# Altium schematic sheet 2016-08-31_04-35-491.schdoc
size 331 x 134 mm; SheetNumber: 1; SheetTotal: 1
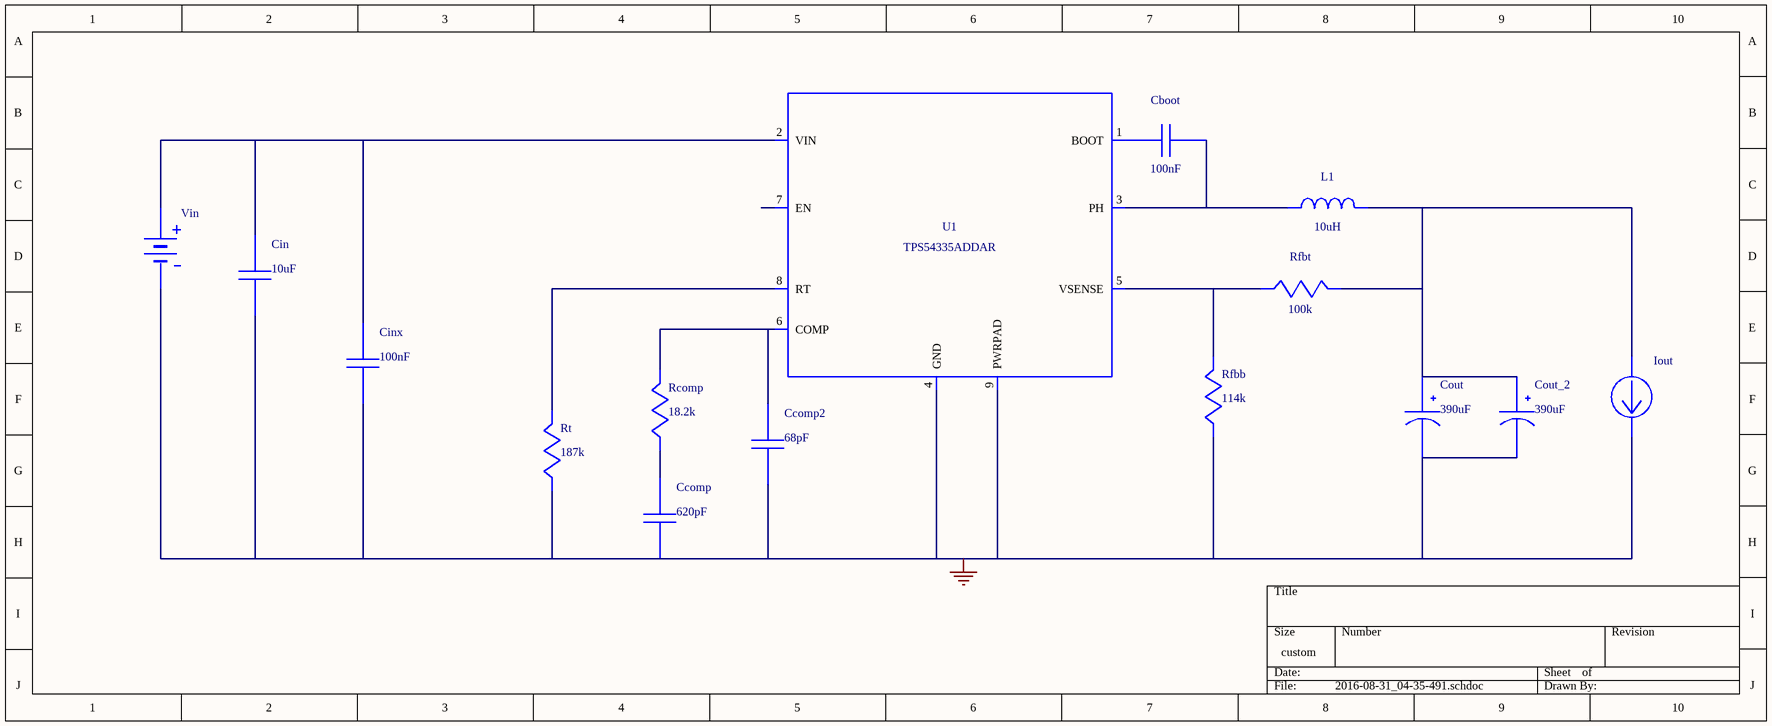
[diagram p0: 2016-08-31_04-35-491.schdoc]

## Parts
Cboot  value 100nF  (hidden comment: C0805C104K5RACTU)
Ccomp  value 620pF  (hidden comment: CL21C621JBCNNNC)
Ccomp2  value 68pF  (hidden comment: C0805C680K5GACTU)
Cin  value 10uF  (hidden comment: GRM31CR71E106KA12L)
Cinx  value 100nF  (hidden comment: C0805C104K5RACTU)
Cout  value 390uF  (hidden comment: APXF2R5ARA391MF61G)
Cout_2  value 390uF  (hidden comment: APXF2R5ARA391MF61G)
Iout  WB_CURRENT_LOAD  (value not drawn)
L1  value 10uH  (hidden comment: SRU1038-100Y)
Rcomp  value 18.2k  (hidden comment: CRCW040218K2FKED)
Rfbb  value 114k  (hidden comment: RT0805BRD07114KL)
Rfbt  value 100k  (hidden comment: CRCW0402100KFKED)
Rt  value 187k  (hidden comment: CRCW0402187KFKED)
U1  TPS54335ADDAR
Vin  WB_BATTERY  (value not drawn)

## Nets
0: Ccomp.2 Ccomp2.2 Cin.2 Cinx.2 Cout.2(-) Cout_2.2(-) Iout.2(-) Rfbb.2 Rt.2 U1.4(GND) U1.9(PWRPAD) Vin.2(-)
NetCboot_1: Cboot.1 U1.1(BOOT)
NetCboot_2: Cboot.2 L1.1 U1.3(PH)
NetCcomp2_1: Ccomp2.1 Rcomp.1 U1.6(COMP)
NetCcomp_1: Ccomp.1 Rcomp.2
NetCin_1: Cin.1 Cinx.1 U1.2(VIN) Vin.1(+)
NetCout_1: Cout.1(+) Cout_2.1(+) Iout.1(+) L1.2 Rfbt.1
NetRfbb_1: Rfbb.1 Rfbt.2 U1.5(VSENSE)
NetRt_1: Rt.1 U1.8(RT)

Not connected (* = marked no-connect by the designer): U1 7(EN)

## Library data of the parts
Cboot Cinx = C0805C104K5RACTU: Manufacturer Name: Kemet
Ccomp = CL21C621JBCNNNC: Manufacturer Name: Samsung Electro-Mechanics
Ccomp2 = C0805C680K5GACTU: Manufacturer Name: Kemet
Cin = GRM31CR71E106KA12L: GRM31CR71E106KA1; Manufacturer Name: MuRata
Cout Cout_2 = APXF2R5ARA391MF61G: APXF2R5ARA391MF6; Manufacturer Name: Chemi-Con
L1 = SRU1038-100Y: Manufacturer Name: Bourns
Rcomp = CRCW040218K2FKED: Manufacturer Name: Vishay-Dale
Rfbb = RT0805BRD07114KL: Manufacturer Name: Yageo America
Rfbt = CRCW0402100KFKED: Manufacturer Name: Vishay-Dale
Rt = CRCW0402187KFKED: Manufacturer Name: Vishay-Dale
U1 = TPS54335ADDAR: Manufacturer Name: Texas Instruments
